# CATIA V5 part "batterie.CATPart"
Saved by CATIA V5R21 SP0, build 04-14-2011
Part number: batterie
Bounding box of the stored display mesh (mm): x -39 to 39, y -26.5 to 26.5, z 0 to 24
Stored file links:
  C:\Users\zerma\Pictures\CAO\batterie.CATPart
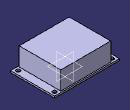
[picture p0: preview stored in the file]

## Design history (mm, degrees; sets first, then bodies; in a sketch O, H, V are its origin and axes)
Body1 (main body)
  Sketch1 on xy-plane, origin (0, 0, 0), H (1, 0, 0), V (0, 1, 0)
    line L1 (-39, 26.5) -> (39, 26.5)
    line L2 (-39, -26.5) -> (-39, 26.5)
    circle A1 centre (-34.4, 21.9) radius 2.3
    point P4 (-34.4, 21.9)
    point P5 (-39, 53)
    point P6 (-39, 0)
    line L3 (-39, -26.5) -> (39, -26.5)
    point P7 (39, -26.5)
    line L4 (39, 26.5) -> (39, -26.5)
    point P8 (39, -26.5)
    circle A2 centre (34.4, 21.9) radius 2.3
    circle A3 centre (34.4, -21.9) radius 2.3
    circle A4 centre (-34.4, -21.9) radius 2.3
    length L1 = 78
    length L2 = 53
    radius A1 = 2.3
    distance P4 L1 = 4.6
    distance P4 L2 = 4.6
    horizontal: L1 H, L3 H
    vertical: L2 V, L4 V
    symmetry: L1 L3 H, L2 L4 V, A1 A2 V, A2 A3 H, A3 A4 V
    coincidence: P8 L3, P7 P8
  Pad1: profile Sketch1, direction (0, 0, 1), length 2
  Sketch2 on end face of Pad1, origin (0, 0, 2), H (1, 0, 0), V (0, 1, 0)
    line L1 (30, 25) -> (30, -25)
    line L2 (30, -25) -> (-30, -25)
    line L3 (-30, -25) -> (-30, 25)
    line L4 (-30, 25) -> (30, 25)
    length L1 = 50
    vertical: L1 V, L3 V
    horizontal: L2 H, L4 H
    equidistance: L1 L3 O, L2 L4 O
  Pad2: profile Sketch2, direction (0, 0, 1), length 22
